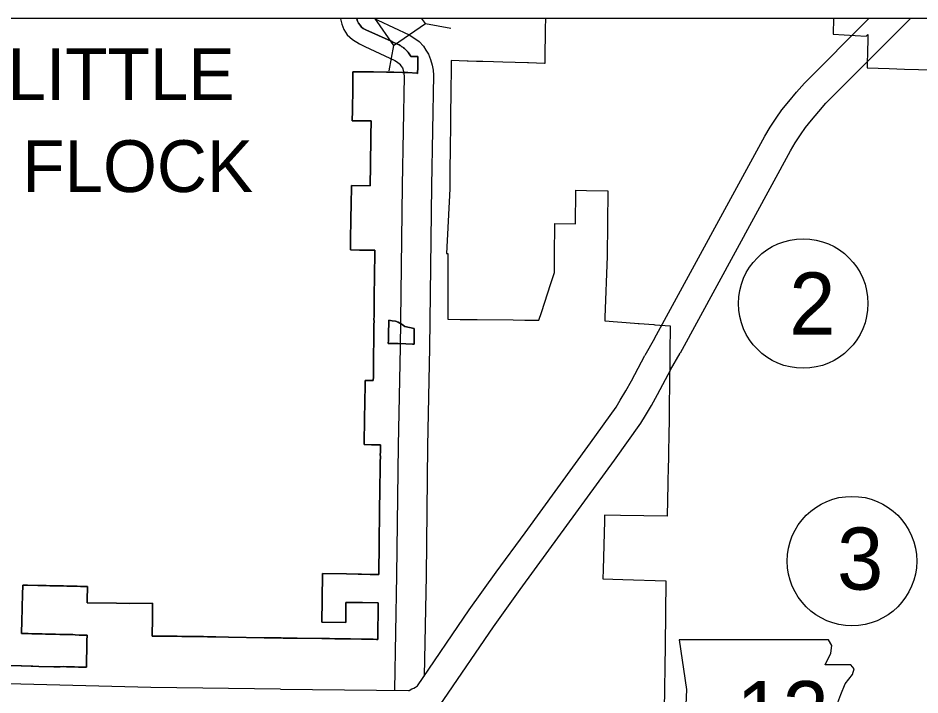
# Model space of a CAD drawing. Extents: x 670147 to 673275, y 705573 to 707613.
# Drawn here: x 670561.9 to 670699.8, y 707418.2 to 707521.7 of the extents above; entities that cross this region are included whole.
import ezdxf

# ---------------------------------------------------------------- set-up
doc = ezdxf.new("R2010")
doc.units = 0
for name, color, linetype in [('10', 7, 'Continuous'), ('15', 7, 'Continuous'), ('20', 7, 'Continuous'), ('21', 7, 'Continuous'), ('27', 7, 'Continuous'), ('6', 7, 'Continuous'), ('R_NoPlot', 7, 'Continuous')]:
    doc.layers.add(name, color=color, linetype=linetype)

msp = doc.modelspace()

# ---------------------------------------------------------------- linework, layer by layer
at = {"layer": '10'}
for points in [[(670611.19, 707521.73), (670611.2, 707521.59), (670611.41, 707520.78), (670611.74, 707520), (670612.22, 707519.15), (670613.05, 707518.47), (670614.13, 707517.79), (670614.94, 707517.38), (670619.53, 707515.22), (670619.91, 707514.98), (670620.25, 707514.73), (670620.31, 707514.67), (670620.45, 707514.44), (670620.68, 707514.09), (670620.74, 707513.94), (670620.86, 707513.51), (670620.92, 707513.2), (670620.94, 707512.86), (670620.62, 707496.12), (670620.33, 707471.36)], [(670616.32, 707521.73), (670616.35, 707521.71), (670616.92, 707521.42), (670621.7, 707519.17), (670622.43, 707518.71), (670623.24, 707518.13), (670623.91, 707517.41), (670624.25, 707516.84), (670624.69, 707516.18), (670625, 707515.4), (670625.25, 707514.52), (670625.39, 707513.74), (670625.44, 707512.97), (670625.12, 707496.05), (670624.83, 707471.31)], [(670620.33, 707471.38), (670620.04, 707456.34), (670619.8, 707436.52), (670619.48, 707418.99)], [(670624.83, 707471.29), (670624.54, 707456.27), (670624.3, 707436.45), (670624.02, 707421.08)], [(670602.03, 707419.11), (670582.21, 707419.36), (670562.34, 707419.84), (670542.08, 707420.29), (670503.08, 707420.89), (670487.93, 707421.21)]]:
    msp.add_lwpolyline(points, dxfattribs=at)
at = {"layer": '15'}
for points in [[(670659.24, 707472.7), (670676.1, 707503.67), (670676.93, 707505.04), (670677.82, 707506.4), (670678.72, 707507.68), (670679.76, 707508.99), (670680.95, 707510.38), (670682.15, 707511.76), (670692.06, 707521.73)], [(670663.19, 707470.54), (670680, 707501.43), (670680.73, 707502.64), (670681.54, 707503.87), (670682.32, 707504.99), (670683.23, 707506.13), (670684.35, 707507.44), (670685.45, 707508.69), (670698.41, 707521.73)], [(670657.78, 707470.18), (670659.27, 707472.75)], [(670623.01, 707419.6), (670630.91, 707431.2), (670635.02, 707436.96), (670639.44, 707442.99), (670649.44, 707456.76), (670653.35, 707462.24), (670653.98, 707463.3), (670654.86, 707464.72), (670655.7, 707466.26), (670657.74, 707470.11)], [(670661.68, 707467.93), (670663.16, 707470.49)], [(670626.22, 707416.32), (670627.01, 707417.49), (670634.6, 707428.62), (670638.66, 707434.32), (670643.07, 707440.33), (670653.1, 707454.13), (670657.12, 707459.78), (670657.83, 707460.96), (670658.76, 707462.46), (670659.67, 707464.14), (670661.72, 707468)], [(670602.03, 707419.11), (670621.61, 707418.89), (670621.69, 707418.9), (670621.71, 707418.91), (670622.13, 707419.12), (670622.44, 707419.25), (670622.68, 707419.39), (670623.01, 707419.6)]]:
    msp.add_lwpolyline(points, dxfattribs=at)
at = {"layer": '20'}
for p, q in [((670624.2, 707520.89), (670628.09, 707520.18)), ((670619.31, 707517.52), (670618.59, 707513.63))]:
    msp.add_line(p, q, dxfattribs=at)
msp.add_lwpolyline([(670616.41, 707521.73), (670619.31, 707517.52), (670624.2, 707520.89), (670623.62, 707521.73)], dxfattribs=at)
at = {"layer": '21'}
msp.add_lwpolyline([(670662.99, 707426.64), (670664.13, 707419.03), (670663.62, 707407.48), (670664.64, 707406.85), (670666.54, 707406.85), (670666.54, 707402.79), (670682.53, 707402.79), (670683.29, 707404.43), (670683.03, 707407.1), (670683.41, 707410.14), (670684.81, 707412.56), (670685.7, 707414.33), (670686.97, 707416.24), (670687.73, 707418.27), (670688.36, 707419.91), (670689.5, 707421.31), (670689.76, 707422.2), (670689.25, 707422.83), (670685.32, 707422.83), (670686.21, 707424.61), (670686.33, 707425.75), (670685.81, 707426.63)], close=True, dxfattribs=at)
at = {"layer": '27'}
for centre in [(670681.96, 707478.07), (670689.42, 707438.68)]:
    msp.add_circle(centre, 9.9, dxfattribs=at)
at = {"layer": '6'}
for points in [[(670620.33, 707517.53), (670620.19, 707517.61), (670619.92, 707517.74), (670619.7, 707517.84), (670619.45, 707517.96), (670619.24, 707518.05), (670618.96, 707518.18), (670615.1, 707519.92), (670614.69, 707520.13), (670614.44, 707520.33), (670614.2, 707520.62), (670613.98, 707520.95), (670613.82, 707521.27), (670613.7, 707521.6), (670613.67, 707521.73)], [(670613.67, 707521.73), (670613.7, 707521.6), (670613.82, 707521.27), (670613.98, 707520.95), (670614.2, 707520.62), (670614.44, 707520.33), (670614.69, 707520.13), (670615.1, 707519.92), (670618.96, 707518.18), (670619.24, 707518.05), (670619.45, 707517.96), (670619.7, 707517.84), (670619.92, 707517.74), (670620.19, 707517.61), (670620.33, 707517.53), (670620.45, 707517.46), (670620.61, 707517.35), (670620.73, 707517.27), (670620.85, 707517.17), (670620.98, 707517.06), (670621.1, 707516.96), (670621.21, 707516.86), (670621.32, 707516.74), (670621.41, 707516.65), (670621.47, 707516.57), (670621.54, 707516.49), (670621.62, 707516.4), (670621.73, 707516.23), (670621.82, 707516.11), (670621.93, 707515.93), (670621.96, 707515.87), (670623.04, 707515.86), (670623.03, 707515.43), (670623.03, 707515.4), (670623.02, 707514.42), (670623.02, 707514.23), (670623.01, 707513.27), (670622.89, 707513.31), (670621.51, 707513.41), (670620.67, 707513.42), (670619.36, 707513.44), (670618.23, 707513.45)], [(670642.55, 707521.73), (670642.55, 707521.64), (670642.53, 707520.12), (670642.5, 707518.56), (670642.48, 707516.97), (670642.45, 707515.36), (670642.44, 707514.8), (670642.41, 707514.8), (670639.94, 707514.87), (670639.8, 707514.87), (670636.05, 707514.98), (670634.63, 707515.02), (670632.98, 707515.07), (670632.58, 707515.08), (670632.55, 707515.08), (670632.15, 707515.1), (670632.01, 707515.1), (670630.73, 707515.14), (670630.59, 707515.14), (670628.12, 707515.22), (670628.11, 707514.35), (670628.07, 707510.19), (670628.03, 707507.07), (670628.02, 707505.6), (670627.96, 707501.63), (670627.93, 707498.61), (670627.95, 707495.63), (670627.42, 707485.72), (670627.63, 707485.71), (670627.6, 707482.88), (670627.63, 707475.93), (670627.63, 707475.66), (670629.51, 707475.64), (670629.65, 707475.64), (670632.09, 707475.62), (670637.64, 707475.55), (670639.39, 707475.53), (670639.88, 707475.52), (670641.53, 707475.5), (670641.93, 707476.72), (670643.36, 707481.14), (670643.91, 707482.81), (670643.93, 707484.23), (670643.95, 707485.42), (670644, 707490.31), (670647.16, 707490.27), (670647.17, 707490.39), (670647.18, 707495.09), (670647.18, 707495.38), (670648.85, 707495.34), (670652.07, 707495.28), (670651.97, 707485.31), (670651.64, 707475.95), (670651.62, 707475.41), (670656.17, 707475.06), (670656.74, 707475.02), (670656.87, 707475.01), (670659.12, 707474.84), (670659.29, 707474.82), (670661.6, 707474.65), (670661.6, 707473.57), (670661.58, 707471.67), (670661.57, 707470.3), (670661.56, 707469.44), (670661.55, 707467.85), (670661.54, 707467.41), (670661.54, 707467.01), (670661.53, 707465.34), (670661.49, 707462.86), (670661.45, 707460.41), (670661.42, 707457.83), (670661.38, 707455.47), (670661.38, 707455.24), (670661.37, 707455.02), (670661.3, 707452.32), (670661.29, 707451.53), (670661.27, 707450.75), (670661.26, 707450.49), (670661.14, 707445.53), (670654.04, 707445.66), (670651.59, 707445.7), (670651.56, 707444.82), (670651.37, 707437.38), (670651.33, 707435.95), (670654.37, 707435.86), (670660.98, 707435.67), (670660.84, 707425.78), (670660.72, 707415.86)], [(670686.59, 707521.73), (670686.56, 707519.26), (670691.58, 707518.94), (670691.6, 707518.94), (670691.85, 707519.21), (670691.83, 707518.12), (670691.83, 707518.05), (670691.83, 707517.99), (670691.82, 707517), (670691.77, 707514.27), (670691.77, 707514.09)], [(670617.32, 707455.36), (670617.32, 707456.47), (670615.94, 707456.47), (670614.82, 707456.5), (670614.81, 707456.5), (670614.82, 707456.61), (670614.83, 707457.23), (670614.84, 707457.76), (670614.85, 707458.28), (670614.86, 707458.81), (670614.87, 707459.34), (670614.88, 707459.86), (670614.89, 707460.38), (670614.89, 707460.91), (670614.9, 707461.43), (670614.91, 707461.96), (670614.92, 707462.49), (670614.93, 707463.01), (670614.94, 707463.54), (670614.95, 707464.06), (670614.96, 707464.58), (670614.97, 707465.11), (670614.97, 707466.31), (670615.32, 707466.31), (670616.22, 707466.28), (670616.24, 707466.84), (670616.25, 707467.37), (670616.25, 707467.89), (670616.26, 707468.42), (670616.26, 707468.95), (670616.27, 707469.47), (670616.27, 707469.99), (670616.28, 707470.52), (670616.28, 707471.04), (670616.29, 707471.57), (670616.29, 707472.1), (670616.3, 707472.62), (670616.31, 707473.14), (670616.32, 707473.67), (670616.32, 707474.19), (670616.33, 707474.72), (670616.34, 707475.46), (670616.33, 707475.52), (670616.34, 707476.25), (670616.34, 707477.52), (670616.37, 707479.52), (670616.4, 707481.95), (670616.46, 707486.22), (670614.1, 707486.25), (670612.74, 707486.27), (670612.75, 707486.67), (670612.76, 707488.4), (670612.8, 707490.35), (670612.81, 707491.26), (670612.83, 707493.04), (670612.88, 707496.14), (670615.74, 707496.06), (670615.78, 707499.3), (670615.82, 707500.99), (670615.85, 707501.76), (670615.86, 707502.61), (670615.84, 707503.73), (670615.89, 707505.99), (670615.69, 707506), (670613.92, 707506), (670613.01, 707506), (670613.05, 707507.6), (670613.08, 707511.05), (670613.08, 707511.46), (670613.09, 707512.1), (670613.11, 707513.51), (670616.24, 707513.48), (670618.23, 707513.45), (670619.36, 707513.44), (670620.67, 707513.42), (670621.51, 707513.41), (670622.89, 707513.31), (670623.01, 707513.27), (670623.02, 707514.23), (670623.02, 707514.42), (670623.03, 707515.4), (670623.03, 707515.43), (670623.04, 707515.86), (670621.96, 707515.87), (670621.93, 707515.93), (670621.82, 707516.11), (670621.73, 707516.23), (670621.62, 707516.4), (670621.54, 707516.49), (670621.47, 707516.57), (670621.41, 707516.65), (670621.32, 707516.74), (670621.21, 707516.86), (670621.1, 707516.96), (670620.98, 707517.06), (670620.85, 707517.17), (670620.73, 707517.27), (670620.61, 707517.35), (670620.45, 707517.46), (670620.33, 707517.53)], [(670691.77, 707514.09), (670695.09, 707514), (670697.46, 707513.93), (670701.76, 707513.8), (670705.99, 707513.72), (670707.3, 707513.7), (670707.71, 707513.69), (670710.97, 707513.63), (670711.73, 707513.62), (670716.91, 707513.51)], [(670618.23, 707513.45), (670616.24, 707513.48), (670613.11, 707513.51), (670613.09, 707512.1), (670613.08, 707511.46), (670613.08, 707511.05), (670613.05, 707507.6), (670613.01, 707506), (670613.92, 707506), (670615.69, 707506), (670615.89, 707505.99), (670615.84, 707503.73), (670615.86, 707502.61), (670615.85, 707501.76), (670615.82, 707500.99), (670615.78, 707499.3), (670615.74, 707496.06), (670612.88, 707496.14), (670612.83, 707493.04), (670612.81, 707491.26), (670612.8, 707490.35), (670612.76, 707488.4), (670612.75, 707486.67), (670612.74, 707486.27), (670614.1, 707486.25), (670616.46, 707486.22), (670616.4, 707481.95), (670616.37, 707479.52), (670616.34, 707477.52), (670616.34, 707476.25), (670616.33, 707475.52), (670616.34, 707475.46), (670616.33, 707474.72), (670616.32, 707474.19), (670616.32, 707473.67), (670616.31, 707473.14), (670616.3, 707472.62), (670616.29, 707472.1), (670616.29, 707471.57), (670616.28, 707471.04), (670616.28, 707470.52), (670616.27, 707469.99), (670616.27, 707469.47), (670616.26, 707468.95), (670616.26, 707468.42), (670616.25, 707467.89), (670616.25, 707467.37), (670616.24, 707466.84), (670616.22, 707466.28), (670615.32, 707466.31), (670614.97, 707466.31), (670614.97, 707465.11), (670614.96, 707464.58), (670614.95, 707464.06), (670614.94, 707463.54), (670614.93, 707463.01), (670614.92, 707462.49), (670614.91, 707461.96), (670614.9, 707461.43), (670614.89, 707460.91), (670614.89, 707460.38), (670614.88, 707459.86), (670614.87, 707459.34), (670614.86, 707458.81), (670614.85, 707458.28), (670614.84, 707457.76), (670614.83, 707457.23), (670614.82, 707456.61), (670614.81, 707456.5), (670614.82, 707456.5), (670615.94, 707456.47), (670617.32, 707456.47), (670617.32, 707455.36), (670617.3, 707454.98), (670617.31, 707454.6), (670617.3, 707453.85), (670617.28, 707453.15), (670617.27, 707452.38), (670617.26, 707451.64), (670617.25, 707450.99), (670617.24, 707450.59), (670617.24, 707450.5), (670617.24, 707449.98), (670617.23, 707449.39), (670617.22, 707448.81), (670617.21, 707448.26), (670617.2, 707447.78), (670617.19, 707447.22), (670617.18, 707446.55), (670617.18, 707446.36), (670617.18, 707446.25), (670617.16, 707444.75), (670617.14, 707443.01), (670617.11, 707440.32), (670617.08, 707437.79), (670617.06, 707436.81), (670617.05, 707436.63), (670615.73, 707436.65), (670614.4, 707436.67), (670613.89, 707436.67)], [(670563.34, 707434.98), (670564.95, 707434.95), (670565.7, 707434.93), (670566.23, 707434.92), (670566.75, 707434.91), (670567.28, 707434.9), (670567.49, 707434.9), (670567.8, 707434.89), (670568.33, 707434.88), (670568.85, 707434.87), (670569.38, 707434.86), (670569.9, 707434.85), (670570.43, 707434.83), (670570.95, 707434.82), (670571.48, 707434.81), (670572, 707434.8), (670572.52, 707434.79), (670572.52, 707434.72), (670572.51, 707433.94), (670572.5, 707433.56), (670572.48, 707432.66), (670572.48, 707432.28), (670576.98, 707432.22), (670578.91, 707432.2), (670582.47, 707432.24), (670582.45, 707431.63), (670582.45, 707430), (670582.41, 707427.22), (670584.72, 707427.2), (670585.51, 707427.19), (670586.25, 707427.18), (670586.96, 707427.17), (670587.35, 707427.15), (670587.68, 707427.16), (670588.34, 707427.14), (670588.98, 707427.13), (670589.62, 707427.13), (670590.25, 707427.12), (670590.89, 707427.11), (670591.53, 707427.1), (670592.15, 707427.09), (670594.11, 707427.04), (670599.55, 707426.95), (670599.8, 707426.95), (670601.14, 707426.93), (670602.14, 707426.93), (670602.46, 707426.91), (670604.59, 707426.88), (670608.35, 707426.83), (670609.51, 707426.82), (670610.35, 707426.8), (670610.74, 707426.8), (670611.15, 707426.79), (670611.52, 707426.78), (670611.9, 707426.78), (670612.01, 707426.78), (670612.27, 707426.77), (670612.72, 707426.77), (670614.43, 707426.74), (670614.47, 707426.74), (670615.47, 707426.73), (670616.19, 707426.72), (670616.71, 707426.71), (670616.92, 707426.71), (670616.99, 707432.29), (670614.57, 707432.33), (670612.04, 707432.34), (670612.04, 707429.31), (670608.36, 707429.36), (670608.42, 707432.77), (670608.46, 707436.77), (670612.14, 707436.71), (670613.89, 707436.67), (670614.4, 707436.67), (670615.73, 707436.65), (670617.05, 707436.63), (670617.06, 707436.81), (670617.08, 707437.79), (670617.11, 707440.32), (670617.14, 707443.01), (670617.16, 707444.75), (670617.18, 707446.25), (670617.18, 707446.36), (670617.18, 707446.55), (670617.19, 707447.22), (670617.2, 707447.78), (670617.21, 707448.26), (670617.22, 707448.81), (670617.23, 707449.39), (670617.24, 707449.98), (670617.24, 707450.5), (670617.24, 707450.59), (670617.25, 707450.99), (670617.26, 707451.64), (670617.27, 707452.38), (670617.28, 707453.15), (670617.3, 707453.85), (670617.31, 707454.6), (670617.3, 707454.98), (670617.32, 707455.36)], [(670613.89, 707436.67), (670612.14, 707436.71), (670608.46, 707436.77), (670608.42, 707432.77), (670608.36, 707429.36), (670612.04, 707429.31), (670612.04, 707432.34), (670614.57, 707432.33), (670616.99, 707432.29), (670616.92, 707426.71), (670616.71, 707426.71), (670616.19, 707426.72), (670615.47, 707426.73), (670614.47, 707426.74), (670614.43, 707426.74), (670612.72, 707426.77), (670612.27, 707426.77), (670612.01, 707426.78), (670611.9, 707426.78), (670611.52, 707426.78), (670611.15, 707426.79), (670610.74, 707426.8), (670610.35, 707426.8), (670609.51, 707426.82), (670608.35, 707426.83), (670604.59, 707426.88), (670602.46, 707426.91), (670602.14, 707426.93), (670601.14, 707426.93), (670599.8, 707426.95), (670599.55, 707426.95), (670594.11, 707427.04), (670592.15, 707427.09), (670591.53, 707427.1), (670590.89, 707427.11), (670590.25, 707427.12), (670589.62, 707427.13), (670588.98, 707427.13), (670588.34, 707427.14), (670587.68, 707427.16), (670587.35, 707427.15), (670586.96, 707427.17), (670586.25, 707427.18), (670585.51, 707427.19), (670584.72, 707427.2), (670582.41, 707427.22), (670582.45, 707430), (670582.45, 707431.63), (670582.47, 707432.24), (670578.91, 707432.2), (670576.98, 707432.22), (670572.48, 707432.28), (670572.48, 707432.66), (670572.5, 707433.56), (670572.51, 707433.94), (670572.52, 707434.72), (670572.52, 707434.79), (670572, 707434.8), (670571.48, 707434.81), (670570.95, 707434.82), (670570.43, 707434.83), (670569.9, 707434.85), (670569.38, 707434.86), (670568.85, 707434.87), (670568.33, 707434.88), (670567.8, 707434.89), (670567.49, 707434.9), (670567.28, 707434.9), (670566.75, 707434.91), (670566.23, 707434.92), (670565.7, 707434.93), (670564.95, 707434.95), (670563.34, 707434.98), (670563.01, 707434.99), (670562.62, 707435), (670562.58, 707433.51), (670562.53, 707431.69), (670562.52, 707431.31), (670562.48, 707429.59), (670562.42, 707427.6), (670562.91, 707427.59), (670563.47, 707427.58), (670564.03, 707427.57), (670564.55, 707427.56), (670565.07, 707427.54), (670565.58, 707427.53), (670566.1, 707427.52), (670566.62, 707427.51), (670567.14, 707427.5), (670567.51, 707427.49), (670567.65, 707427.49), (670568.32, 707427.47), (670568.7, 707427.46), (670569.26, 707427.45), (670569.47, 707427.45), (670569.78, 707427.44), (670570.07, 707427.43), (670570.3, 707427.43), (670570.66, 707427.38), (670571.26, 707427.36)], [(670557.36, 707422.79), (670562.37, 707422.67), (670562.44, 707422.67), (670562.43, 707422.64), (670563.93, 707422.61), (670564.17, 707422.6), (670565.08, 707422.58), (670567.4, 707422.51), (670568.04, 707422.5), (670568.37, 707422.51), (670568.79, 707422.54), (670569.31, 707422.52), (670569.93, 707422.51), (670570.55, 707422.49), (670571.16, 707422.47), (670571.78, 707422.46), (670572.35, 707422.44), (670572.36, 707422.44), (670572.38, 707423.25), (670572.39, 707424.1), (670572.39, 707424.1), (670572.39, 707424.24), (670572.4, 707424.47), (670572.4, 707424.47), (670572.41, 707425.17), (670572.42, 707425.3), (670572.43, 707425.98), (670572.43, 707426.13), (670572.43, 707426.13), (670572.43, 707426.25), (670572.44, 707426.44), (670572.45, 707426.44), (670572.45, 707426.5), (670572.46, 707427.33), (670571.86, 707427.35), (670571.26, 707427.36), (670570.66, 707427.38), (670570.3, 707427.43), (670570.07, 707427.43), (670569.78, 707427.44), (670569.47, 707427.45), (670569.26, 707427.45), (670568.7, 707427.46), (670568.32, 707427.47), (670567.65, 707427.49), (670567.51, 707427.49), (670567.14, 707427.5), (670566.62, 707427.51), (670566.1, 707427.52), (670565.58, 707427.53), (670565.07, 707427.54), (670564.55, 707427.56), (670564.03, 707427.57), (670563.47, 707427.58), (670562.91, 707427.59), (670562.42, 707427.6), (670562.48, 707429.59), (670562.52, 707431.31), (670562.53, 707431.69), (670562.58, 707433.51), (670562.62, 707435), (670563.01, 707434.99), (670563.34, 707434.98)], [(670571.26, 707427.36), (670571.86, 707427.35), (670572.46, 707427.33), (670572.45, 707426.5), (670572.45, 707426.44), (670572.44, 707426.44), (670572.43, 707426.25), (670572.43, 707426.13), (670572.43, 707426.13), (670572.43, 707425.98), (670572.42, 707425.3), (670572.41, 707425.17), (670572.4, 707424.47), (670572.4, 707424.47), (670572.39, 707424.24), (670572.39, 707424.1), (670572.39, 707424.1), (670572.38, 707423.25), (670572.36, 707422.44)], [(670572.36, 707422.44), (670572.35, 707422.44), (670571.78, 707422.46), (670571.16, 707422.47), (670570.55, 707422.49), (670569.93, 707422.51), (670569.31, 707422.52), (670568.79, 707422.54), (670568.37, 707422.51), (670568.04, 707422.5), (670567.4, 707422.51), (670565.08, 707422.58), (670564.17, 707422.6), (670563.93, 707422.61), (670562.43, 707422.64), (670562.44, 707422.67), (670562.37, 707422.67), (670557.36, 707422.79)]]:
    msp.add_lwpolyline(points, dxfattribs=at)
for points in [[(670622.49, 707471.87), (670622.49, 707471.96), (670622.5, 707474.23), (670621.05, 707474.57), (670620.66, 707474.87), (670620.03, 707475.2), (670619.62, 707475.38), (670619.11, 707475.41), (670618.6, 707475.5), (670618.61, 707475.42), (670618.59, 707474.64), (670618.57, 707474.09), (670618.56, 707473.54), (670618.54, 707473), (670618.53, 707472.46), (670618.52, 707471.98), (670619.18, 707471.97), (670620.02, 707471.94), (670621.2, 707471.9), (670622.22, 707471.86)], [(670622.49, 707471.87), (670622.22, 707471.86), (670621.2, 707471.9), (670620.02, 707471.94), (670619.18, 707471.97), (670618.52, 707471.98), (670618.53, 707472.46), (670618.54, 707473), (670618.56, 707473.54), (670618.57, 707474.09), (670618.59, 707474.64), (670618.61, 707475.42), (670618.6, 707475.5), (670619.11, 707475.41), (670619.62, 707475.38), (670620.03, 707475.2), (670620.66, 707474.87), (670621.05, 707474.57), (670622.5, 707474.23), (670622.49, 707471.96)]]:
    msp.add_lwpolyline(points, close=True, dxfattribs=at)
at = {"layer": 'R_NoPlot'}
msp.add_lwpolyline([(670257.19, 707521.73), (670842.89, 707521.73), (670842.89, 706992.57), (670257.19, 706992.57)], close=True, dxfattribs=at)

# ---------------------------------------------------------------- texts
at = {"layer": '21'}
msp.add_text('12', height=9.504, dxfattribs=at).set_placement((670671.73, 707410.82))
at = {"layer": '27'}
for s, p in [('2', (670679.83, 707473.32)), ('3', (670687.14, 707434.31))]:
    msp.add_text(s, height=9.5, dxfattribs=at).set_placement(p)
at = {"layer": '6'}
for s, p in [('LITTLE', (670560.29, 707509.18)), ('FLOCK', (670562.54, 707495.12))]:
    msp.add_text(s, height=7.92, dxfattribs=at).set_placement(p)

doc.saveas('drawing.dxf')
